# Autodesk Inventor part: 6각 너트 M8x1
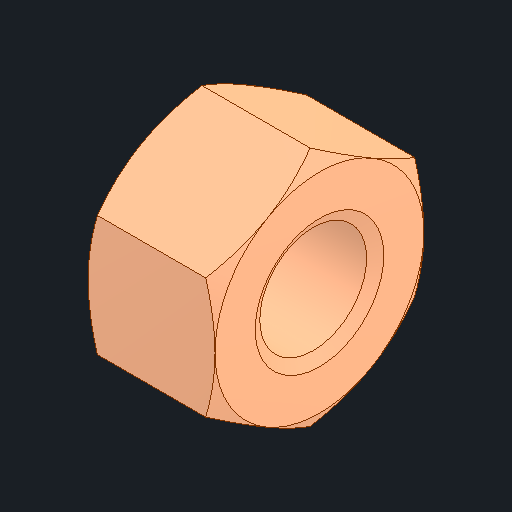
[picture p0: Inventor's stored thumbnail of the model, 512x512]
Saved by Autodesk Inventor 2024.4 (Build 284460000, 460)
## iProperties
Created: 2025-10
Part Number: 6각 너트 M8x1
Material: 강철, 연강
Description: 6각 너트 및 6각 가는 너트
Document SubType Name: Modeling
Designer: user
Density: 7.85 g/cm^3
Appearance: 기본값
Author: jhkim
Sending System: Autodesk Inventor 2026
Preprocessor: ST-DEVELOPER v20.1
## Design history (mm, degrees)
feature "Solid1"
node "솔리드1"
